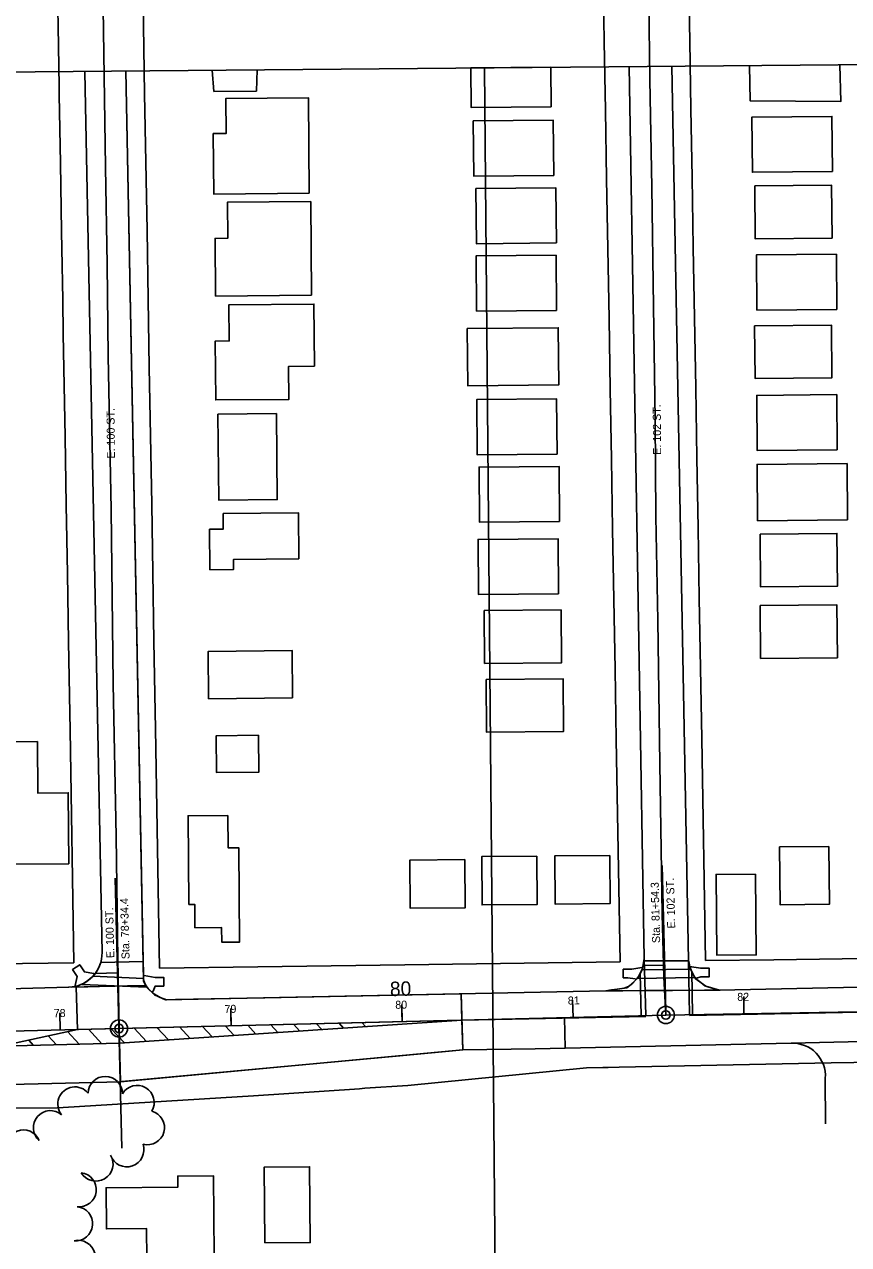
# Model space of a CAD drawing. Extents: x -2233 to 187241, y 4582 to 150524.
# Drawn here: x 107722 to 108204, y 59338 to 60052 of the extents above; entities that cross this region are included whole.
import ezdxf

# ---------------------------------------------------------------- set-up
doc = ezdxf.new("R2010")
doc.units = 0
for name, color, linetype in [('AP_X_Misc', 7, 'Continuous'), ('BLDG', 7, 'Continuous'), ('GE_X_CL_100', 7, 'Continuous'), ('GE_X_CL_20', 7, 'Continuous'), ('GE_X_CL_2000', 7, 'Continuous'), ('GE_X_CL_50', 7, 'Continuous'), ('GRID', 7, 'Continuous'), ('PM_P_CL_Double_Solid', 7, 'Continuous'), ('PM_P_Crosswalk', 7, 'Continuous'), ('PM_P_Stop_Line', 7, 'Continuous'), ('PM_P_Text', 7, 'Continuous'), ('PM_P_Transverse_Line', 7, 'Continuous'), ('PV_P_Curb_Ramp', 7, 'Continuous'), ('ROAD', 7, 'Continuous'), ('ROAD-NAME', 7, 'Continuous'), ('RW_X_Fee_RW', 7, 'Continuous'), ('SG_P_Detection', 7, 'Continuous'), ('TREES', 7, 'Continuous')]:
    doc.layers.add(name, color=color, linetype=linetype)

msp = doc.modelspace()

# ---------------------------------------------------------------- linework, layer by layer
at = {"layer": 'AP_X_Misc'}
for p, q in [((107777.4, 59464.42), (107776.79, 59489.24)), ((107977.97, 59469.36), (107977.59, 59484.73)), ((107978.4, 59451.89), (107977.97, 59469.36)), ((108037.9, 59470.84), (108038.34, 59452.95)), ((107778.17, 59433.26), (107777.4, 59464.42))]:
    msp.add_line(p, q, dxfattribs=at)
for points in [[(107766.67, 59502.99), (107791.56, 59503.61), (107791.6, 59501.45), (107791.64, 59499.23), (107791.71, 59496.02), (107791.75, 59494.08), (107791.9, 59492.12), (107792.6, 59490.62), (107793.06, 59489.64), (107772.26, 59489.13), (107759.22, 59488.81), (107749.68, 59488.57), (107750.52, 59488.76), (107753.33, 59489.41), (107756.64, 59490.75), (107759.25, 59492.38), (107761.56, 59494.34), (107763.24, 59496.24), (107764.82, 59498.6), (107766.01, 59501.06), (107766.46, 59502.29)], [(108062.14, 59486.47), (108065.43, 59486.93), (108068.73, 59487.39), (108072.8, 59487.97), (108075.4, 59488.96), (108078.93, 59492.07), (108081.04, 59494.42), (108082.23, 59496.6), (108083.29, 59498.72), (108083.84, 59500.63), (108084.16, 59502.6), (108084.39, 59503.94), (108086.32, 59503.91), (108093.83, 59503.94), (108099.64, 59503.97), (108105.69, 59504), (108109.18, 59504.02), (108110.44, 59504.02), (108110.79, 59502.7), (108111.31, 59500.44), (108111.91, 59498.78), (108113.05, 59496.47), (108113.98, 59494.57), (108115.39, 59492.97), (108117.71, 59491.22), (108120.1, 59489.41), (108121.76, 59488.74), (108124.36, 59487.99), (108126.93, 59487.25), (108128.82, 59486.81), (108119.85, 59486.76), (108101.15, 59486.66), (108085.09, 59486.58), (108072.06, 59486.52)], [(107977.59, 59484.73), (107862.66, 59482.36), (107810.43, 59481.28), (107805.22, 59481.18), (107801.52, 59482.54), (107797.18, 59485.08), (107794.37, 59487.78), (107793.06, 59489.64), (107782.35, 59489.38), (107776.79, 59489.25), (107776.84, 59487.03), (107778.17, 59433.26), (107779, 59433.33), (107848.71, 59439.82), (107939.5, 59448.27), (107970.55, 59451.16), (107978.4, 59451.89)]]:
    msp.add_lwpolyline(points, close=True, dxfattribs=at)
at = {"layer": 'BLDG'}
msp.add_line((108029.98, 60026.48), (108030.18, 60003.32), dxfattribs=at)
for points in [[(107858.17, 60024.98), (107857.72, 60012.55), (107832.9, 60012.33), (107831.81, 60024.75)], [(108030.18, 60003.32), (107983.41, 60002.91), (107983.21, 60026.07), (108029.98, 60026.48)], [(108146.23, 60027.49), (108146.55, 60006.8), (108199.52, 60006.43), (108198.95, 60027.95)]]:
    msp.add_lwpolyline(points, dxfattribs=at)
for points in [[(107888.61, 59952.75), (107832.79, 59952.27), (107832.48, 59987.66), (107840.02, 59987.72), (107839.84, 60008.18), (107888.12, 60008.6)], [(108031.66, 59963.26), (107984.89, 59962.85), (107984.61, 59995.1), (108031.38, 59995.51)], [(108194.61, 59965.43), (108147.84, 59965.03), (108147.56, 59997.28), (108194.33, 59997.68)], [(108033.2, 59923.7), (107986.44, 59923.3), (107986.16, 59955.55), (108032.92, 59955.95)], [(108149.18, 59957.08), (108194.14, 59957.47), (108194.41, 59926.6), (108149.45, 59926.21)], [(107889.99, 59893.16), (107833.85, 59892.67), (107833.55, 59926.39), (107841.01, 59926.46), (107840.83, 59947.51), (107889.51, 59947.93)], [(108033.3, 59884.28), (107986.53, 59883.88), (107986.25, 59916.12), (108033.02, 59916.53)], [(108197.21, 59884.88), (108150.44, 59884.48), (108150.16, 59916.72), (108196.93, 59917.13)], [(107891.73, 59851.71), (107876.57, 59851.57), (107876.74, 59832.28), (107833.97, 59831.9), (107833.67, 59866.36), (107841.86, 59866.43), (107841.67, 59887.55), (107891.41, 59887.99)], [(107981.09, 59873.7), (108034.26, 59874.16), (108034.55, 59840.73), (107981.38, 59840.27)], [(108149.11, 59875.33), (108194.07, 59875.73), (108194.34, 59844.86), (108149.38, 59844.47)], [(108033.62, 59800.3), (107986.85, 59799.9), (107986.57, 59832.14), (108033.34, 59832.55)], [(108197.44, 59802.78), (108150.67, 59802.37), (108150.39, 59834.62), (108197.15, 59835.03)], [(107869.46, 59823.91), (107869.9, 59773.7), (107835.69, 59773.41), (107835.25, 59823.61)], [(108035.03, 59760.82), (107988.25, 59760.42), (107987.97, 59792.66), (108034.74, 59793.07)], [(108203.49, 59761.75), (108150.84, 59761.29), (108150.55, 59794.28), (108203.21, 59794.74)], [(107882.63, 59738.97), (107844.35, 59738.64), (107844.4, 59732.81), (107830.52, 59732.69), (107830.32, 59756.37), (107838.39, 59756.44), (107838.31, 59765.46), (107882.4, 59765.84)], [(108152.33, 59753.48), (108197.29, 59753.87), (108197.56, 59723), (108152.6, 59722.61)], [(108034.48, 59718.51), (107987.71, 59718.1), (107987.43, 59750.35), (108034.19, 59750.76)], [(108152.31, 59711.68), (108197.27, 59712.07), (108197.54, 59681.19), (108152.58, 59680.8)], [(107990.97, 59708.79), (108035.93, 59709.18), (108036.2, 59678.31), (107991.24, 59677.92)], [(107878.94, 59657.67), (107829.79, 59657.24), (107829.55, 59684.94), (107878.7, 59685.37)], [(107992.11, 59668.51), (108037.07, 59668.9), (108037.34, 59638.03), (107992.38, 59637.64)], [(107729.63, 59632.2), (107729.89, 59602.1), (107747.66, 59602.25), (107748.02, 59560.76), (107707.84, 59560.41), (107707.51, 59598.59), (107704.45, 59598.56), (107704.16, 59631.98)], [(107858.9, 59635.83), (107859.09, 59614.25), (107834.43, 59614.04), (107834.24, 59635.62)], [(107840.99, 59589), (107841.15, 59570.08), (107847.46, 59570.13), (107847.94, 59514.98), (107837.43, 59514.89), (107837.36, 59523.46), (107821.77, 59523.32), (107821.65, 59536.98), (107818.24, 59536.95), (107817.79, 59588.8)], [(108192.58, 59570.8), (108192.88, 59537.01), (108164, 59536.76), (108163.7, 59570.55)], [(107979.7, 59563.19), (107979.94, 59534.97), (107947.75, 59534.69), (107947.5, 59562.91)], [(108021.71, 59565.2), (108021.96, 59536.98), (107989.76, 59536.7), (107989.51, 59564.92)], [(108064.38, 59565.62), (108064.63, 59537.4), (108032.44, 59537.12), (108032.19, 59565.34)], [(108149.7, 59554.72), (108150.11, 59507.46), (108127.04, 59507.26), (108126.63, 59554.52)], [(107862.73, 59339.01), (107862.34, 59383.38), (107888.87, 59383.61), (107889.26, 59339.25)], [(107833.04, 59331.53), (107828.04, 59331.48), (107828.14, 59320.88), (107814.34, 59320.76), (107814.41, 59312.6), (107793.84, 59312.42), (107793.53, 59347.44), (107770.04, 59347.24), (107769.83, 59371.3), (107811.82, 59371.66), (107811.77, 59378.08), (107832.64, 59378.26)]]:
    msp.add_lwpolyline(points, close=True, dxfattribs=at)
at = {"layer": 'GE_X_CL_100'}
for p, q in [((107977.59, 59484.73), (107978.4, 59451.89)), ((108142.92, 59473.09), (108142.75, 59483.09)), ((107843.01, 59466.03), (107842.76, 59476.03)), ((107942.98, 59468.5), (107942.73, 59478.5)), ((108042.95, 59470.96), (108042.7, 59480.96)), ((107743.04, 59463.57), (107742.79, 59473.56))]:
    msp.add_line(p, q, dxfattribs=at)
for centre in [(108097.25, 59472.3), (107777.4, 59464.42)]:
    msp.add_circle(centre, 5, dxfattribs=at)
at = {"layer": 'GE_X_CL_20'}
for p, q in [((108097.25, 59472.3), (108427.33, 59477.99)), ((107777.4, 59464.42), (108097.25, 59472.3)), ((107446.21, 59456.25), (107777.4, 59464.42))]:
    msp.add_line(p, q, dxfattribs=at)
at = {"layer": 'GE_X_CL_2000'}
for p, q in [((108097.25, 59472.3), (108427.33, 59477.99)), ((107777.4, 59464.42), (108097.25, 59472.3)), ((107446.21, 59456.25), (107777.4, 59464.42))]:
    msp.add_line(p, q, dxfattribs=at)
for points in [[(107760.03, 60619.24), (107760.15, 60588.53), (107760.98, 60548.62), (107761.25, 60524.82), (107761.95, 60477.02), (107763.33, 60382.63), (107764.11, 60338.03), (107764.23, 60331.55), (107765.6, 60257.08), (107767.04, 60172.07), (107767.96, 60074.55), (107769.57, 59968.09), (107770.37, 59911.12), (107770.95, 59857.49), (107772.78, 59767.79), (107774, 59666.03), (107775.75, 59576.6), (107776.63, 59504.94), (107777.39, 59464.42)], [(108087.02, 60080.19), (108087.79, 60019.04), (108089.01, 59956.27), (108090.07, 59886.62), (108091.05, 59820.42), (108091.4, 59763.72), (108092.58, 59703.04), (108093.67, 59619.1), (108094.97, 59531.32), (108095.99, 59494.5), (108097.25, 59472.3)]]:
    msp.add_lwpolyline(points, dxfattribs=at)
at = {"layer": 'GE_X_CL_50'}
for p, q in [((108097.19, 59474.8), (108095.1, 59559.69)), ((107777.34, 59466.91), (107775.23, 59552.26)), ((108082.75, 59471.95), (108082.15, 59496.44)), ((108112.76, 59472.57), (108112.33, 59497.94)), ((108042.95, 59470.96), (108042.82, 59475.96)), ((108142.92, 59473.09), (108142.84, 59478.09)), ((107743.04, 59463.57), (107742.91, 59468.57)), ((107843.01, 59466.03), (107842.88, 59471.03)), ((107942.98, 59468.5), (107942.85, 59473.5))]:
    msp.add_line(p, q, dxfattribs=at)
for centre in [(108097.25, 59472.3), (107777.4, 59464.42)]:
    msp.add_circle(centre, 2.5, dxfattribs=at)
at = {"layer": 'GRID'}
for p, q in [((109991.08, 60043.59), (104991.27, 59999.96)), ((107991.16, 60026.14), (108014.7, 57328.47))]:
    msp.add_line(p, q, dxfattribs=at)
at = {"layer": 'PM_P_CL_Double_Solid'}
for p, q in [((108317.9, 59476.1), (108110.99, 59472)), ((107753.03, 59463.81), (107977.97, 59469.36)), ((107777.61, 59455.75), (107977.97, 59469.36)), ((108085.43, 59471.49), (107977.97, 59469.36)), ((107708.26, 59454.04), (107753.03, 59463.81)), ((107708.26, 59454.04), (107777.61, 59455.75))]:
    msp.add_line(p, q, dxfattribs=at)
at = {"layer": 'PM_P_Crosswalk'}
for p, q in [((108083.26, 59498.77), (108111.74, 59499.14)), ((107793.56, 59488.56), (107755.86, 59490.23)), ((107791.65, 59493.65), (107762.15, 59494.96)), ((108080.43, 59493.73), (108114.25, 59494.17))]:
    msp.add_line(p, q, dxfattribs=at)
at = {"layer": 'PM_P_Stop_Line'}
for p, q in [((107763.51, 59496.64), (107776.78, 59496.97)), ((108096.53, 59501.49), (108083.93, 59501.18))]:
    msp.add_line(p, q, dxfattribs=at)
at = {"layer": 'PM_P_Text'}
for p, q in [((108085.42, 59472.01), (108084.6, 59505.32)), ((108110.98, 59472.54), (108110.44, 59504.24)), ((107753.03, 59463.81), (107752.42, 59488.64)), ((107977.97, 59469.36), (107977.72, 59479.36))]:
    msp.add_line(p, q, dxfattribs=at)
at = {"layer": 'PM_P_Transverse_Line'}
for p, q in [((107892.74, 59467.26), (107895.95, 59463.79)), ((107906.06, 59467.59), (107908.76, 59464.66)), ((107919.37, 59467.92), (107921.58, 59465.53)), ((107735.94, 59460.08), (107740.78, 59454.84)), ((107747.27, 59462.56), (107754.1, 59455.17)), ((107759.58, 59463.98), (107767.42, 59455.5)), ((107772.89, 59464.3), (107780.61, 59455.95)), ((107786.21, 59464.63), (107793.43, 59456.82)), ((107799.53, 59464.96), (107806.24, 59457.69)), ((107812.84, 59465.29), (107819.06, 59458.57)), ((107826.16, 59465.62), (107831.87, 59459.44)), ((107839.47, 59465.95), (107844.69, 59460.31)), ((107852.79, 59466.27), (107857.5, 59461.18)), ((107866.11, 59466.6), (107870.32, 59462.05)), ((107879.42, 59466.93), (107883.13, 59462.92)), ((107724.61, 59457.61), (107727.47, 59454.51))]:
    msp.add_line(p, q, dxfattribs=at)
at = {"layer": 'PV_P_Curb_Ramp'}
for points in [[(107751.78, 59489.01), (107751.69, 59489.5), (107752.99, 59494.74), (107750.24, 59498.89), (107754.4, 59501.66), (107757.16, 59497.49), (107762.48, 59496.64), (107762.9, 59496.37), (107763.18, 59496.17), (107762.51, 59495.35), (107761.81, 59494.6), (107760.74, 59493.57), (107759.8, 59492.79), (107758.56, 59491.84), (107757.32, 59491.04), (107756.3, 59490.49), (107755.14, 59490.06), (107753.88, 59489.52), (107752.12, 59489.07)], [(108083.64, 59499.87), (108083.17, 59500.05), (108077.28, 59499.09), (108072.28, 59499.04), (108072.33, 59494.04), (108074.94, 59494.06), (108079.2, 59493.36), (108079.58, 59493.03), (108079.71, 59492.94), (108080.2, 59493.48), (108080.69, 59494.02), (108081.3, 59494.84), (108082.03, 59496.2), (108082.63, 59497.33), (108083.04, 59498.26), (108083.31, 59498.86), (108083.54, 59499.44)], [(108114.86, 59493.52), (108115.24, 59493.85), (108117.63, 59494.64), (108122.63, 59494.68), (108122.59, 59499.68), (108117.59, 59499.64), (108112.25, 59500.53), (108111.77, 59500.39), (108111.38, 59500.25), (108111.62, 59499.43), (108112.05, 59498.5), (108112.61, 59497.36), (108113.15, 59496.27), (108113.57, 59495.39), (108114.03, 59494.49), (108114.53, 59493.78)], [(107791.69, 59495.24), (107792.09, 59495.32), (107798.58, 59494.27), (107803.58, 59494.3), (107803.6, 59489.25), (107798.6, 59489.22), (107797.27, 59486.3), (107796.64, 59485.63), (107795.87, 59486.42), (107795.27, 59486.97), (107794.64, 59487.63), (107794.2, 59488.06), (107793.76, 59488.56), (107793.32, 59489.27), (107793.02, 59489.84), (107792.75, 59490.52), (107792.33, 59491.33), (107792.06, 59491.84), (107791.88, 59492.64), (107791.72, 59493.54), (107791.71, 59494.35), (107791.67, 59494.96)]]:
    msp.add_lwpolyline(points, close=True, dxfattribs=at)
at = {"layer": 'ROAD'}
for p, q in [((107767.45, 59508.92), (107757.32, 60023.84)), ((107791.75, 59494.05), (107781.32, 60024.31)), ((107766.67, 59502.99), (107791.56, 59503.61)), ((108084.62, 59503.9), (108110.44, 59504.02)), ((107511.44, 59482.7), (107747.95, 59488.53)), ((107747.95, 59488.53), (107793.06, 59489.64)), ((108062.17, 59486.47), (108128.5, 59486.8)), ((108170.43, 59455.8), (108244.42, 59457.56)), ((107778.17, 59433.26), (107978.4, 59451.89)), ((107530.86, 59427.16), (107778.17, 59433.26)), ((108190.46, 59435.36), (108190.64, 59408.6))]:
    msp.add_line(p, q, dxfattribs=at)
for points in [[(108075.75, 60026.88), (108084.6, 59505.32), (108083.65, 59499.45), (108081.25, 59494.65), (108077.96, 59490.99), (108074.45, 59488.2), (108062.17, 59486.47), (107804.5, 59481.16), (107798.24, 59484.06), (107793.56, 59488.56), (107791.78, 59492.37), (107781.32, 60024.31)], [(108405.6, 60029.76), (108414.07, 59507.11), (108411.34, 59499.49), (108407.76, 59496.27), (108402.29, 59493.6), (108391.31, 59492.38), (108128.5, 59486.8), (108120.52, 59489.1), (108114.39, 59493.73), (108111.5, 59499.63), (108110.44, 59504.24), (108100.65, 60027.1)], [(108170.43, 59455.8), (108020.69, 59452.57), (107978.4, 59451.89)]]:
    msp.add_lwpolyline(points, dxfattribs=at)
for centre, radius, start, end in [((107747.45, 59508.52), 20, 271.41275, 1.12677), ((108171.38, 59436.69), 19.13, 355.98785, 92.83354)]:
    msp.add_arc(centre, radius, start, end, dxfattribs=at)
at = {"layer": 'RW_X_Fee_RW'}
for p, q in [((107704.07, 59502.23), (107751.06, 59502.89)), ((108193.89, 59444.37), (108610.64, 59451.23)), ((108063.55, 59441.69), (108050.79, 59441.43))]:
    msp.add_line(p, q, dxfattribs=at)
for points in [[(108070.42, 59503.37), (108068.2, 59633.35), (108067.49, 59674.35), (108066.79, 59715.34), (108066.09, 59756.34), (108065.39, 59797.33), (108064.69, 59838.32), (108063.99, 59879.32), (108063.28, 59920.31), (108062.58, 59961.31), (108061.9, 60001.3), (108061.21, 60041.3), (108060.53, 60081.29), (108059.85, 60121.28), (108059.16, 60161.28), (108058.48, 60201.27), (108057.79, 60241.27), (108057.11, 60281.26), (108056.42, 60321.25), (108055.74, 60361.25), (108055.05, 60401.24), (108054.37, 60441.24), (108053.68, 60481.23), (108051.65, 60600.33)], [(108120.42, 59504.07), (108118.19, 59634.06), (108117.49, 59675.05), (108116.79, 59716.04), (108116.09, 59757.04), (108115.39, 59798.03), (108114.68, 59839.03), (108113.98, 59880.02), (108113.28, 59921.01), (108112.58, 59962.01), (108111.9, 60002), (108111.21, 60042), (108110.53, 60081.99), (108109.84, 60121.99), (108109.16, 60161.98), (108108.47, 60201.97), (108107.79, 60241.97), (108107.1, 60281.96), (108106.42, 60321.96), (108105.73, 60361.95), (108105.05, 60401.94), (108104.37, 60441.94), (108103.68, 60481.93), (108101.64, 60601.19)], [(107751.06, 59502.89), (107748.74, 59638.87), (107748.57, 59648.87), (107747.86, 59690.44), (107747.17, 59730.43), (107746.49, 59770.42), (107745.81, 59810.42), (107745.12, 59850.41), (107744.78, 59870.41), (107744.44, 59890.41), (107743.93, 59920.4), (107743.76, 59930.4), (107743.07, 59970.39), (107742.39, 60010.39), (107742.31, 60015.39), (107741.71, 60050.38), (107741.54, 60060.38)], [(107801.12, 59499.59), (107798.73, 59639.57), (107798.56, 59649.57), (107797.85, 59690.97), (107797.17, 59730.96), (107796.49, 59770.96), (107795.8, 59810.95), (107795.46, 59830.95), (107795.12, 59850.94), (107794.44, 59890.94), (107793.76, 59930.93), (107793.41, 59950.93), (107793.07, 59970.93), (107792.39, 60010.92), (107791.71, 60050.91), (107791.45, 60065.91)], [(107801.12, 59499.59), (107858.49, 59500.4), (107901.48, 59501), (107944.48, 59501.61), (107986.43, 59502.19), (108028.42, 59502.78), (108070.42, 59503.37)], [(108120.42, 59504.07), (108160.41, 59504.64), (108200.41, 59505.2), (108240.41, 59505.76), (108280.41, 59506.32), (108320.4, 59506.88), (108360.4, 59507.44), (108400.4, 59508)], [(107946.22, 59431.12), (108050.79, 59441.43), (108193.89, 59444.37)], [(107744.65, 59418.15), (107856.11, 59425.01), (107918.01, 59429.21), (107921.24, 59429.43), (107946.22, 59431.12)], [(107534.38, 59415.64), (107642.13, 59416.92), (107692.12, 59417.52), (107710.12, 59417.74), (107741.2, 59418.11), (107744.65, 59418.15)]]:
    msp.add_lwpolyline(points, dxfattribs=at)
at = {"layer": 'SG_P_Detection'}
msp.add_line((107779.13, 59394.37), (107775.23, 59552.26), dxfattribs=at)
at = {"layer": 'TREES'}
for centre, start, end in [((107769.36, 59426.4), 359.08914, 179.08914), ((107751.59, 59420.26), 39.03154, 219.03154), ((107787.96, 59421.15), 329.40475, 149.40475), ((107737.28, 59406.4), 49.14763, 229.14763), ((107794, 59406.39), 255.08376, 75.08375), ((107721.46, 59395.11), 21.85453, 201.85453), ((107781.96, 59393.5), 198.82733, 18.82733), ((107763.89, 59385.18), 210.65683, 30.65683), ((107754.1, 59370.15), 263.16775, 83.16775), ((107751.99, 59350.26), 264.71364, 84.71364), ((107753.48, 59330.6), 283.98394, 103.98394)]:
    msp.add_arc(centre, 10, start, end, dxfattribs=at)

# ---------------------------------------------------------------- texts
at = {"layer": 'GE_X_CL_100'}
msp.add_text('80', height=8.4, rotation=1.41275, dxfattribs=at).set_placement((107935.92, 59483.33))
at = {"layer": 'GE_X_CL_50'}
for s, rotation, p in [('Sta. 81+54.3', 91.41275, (108093.9, 59514.41)), ('E. 102 ST.', 91.41275, (108102.71, 59522.96)), ('Sta. 78+34.4', 91.41275, (107783.58, 59504.98)), ('E. 100 ST.', 91.41275, (107774.68, 59505.63)), ('81', 1.41275, (108039.94, 59478.39)), ('82', 0.9861, (108139.02, 59480.52)), ('78', 1.41275, (107739.24, 59470.98)), ('79', 1.41275, (107839.13, 59473.44)), ('80', 1.41275, (107939.02, 59475.9))]:
    msp.add_text(s, height=4.68, rotation=rotation, dxfattribs=at).set_placement(p)
at = {"layer": 'ROAD-NAME'}
for s, p in [('E. 100 ST.', (107775.01, 59797.65)), ('E. 102 ST.', (108094.47, 59799.87))]:
    msp.add_text(s, height=4.68, rotation=90.5, dxfattribs=at).set_placement(p)

doc.saveas('drawing.dxf')
